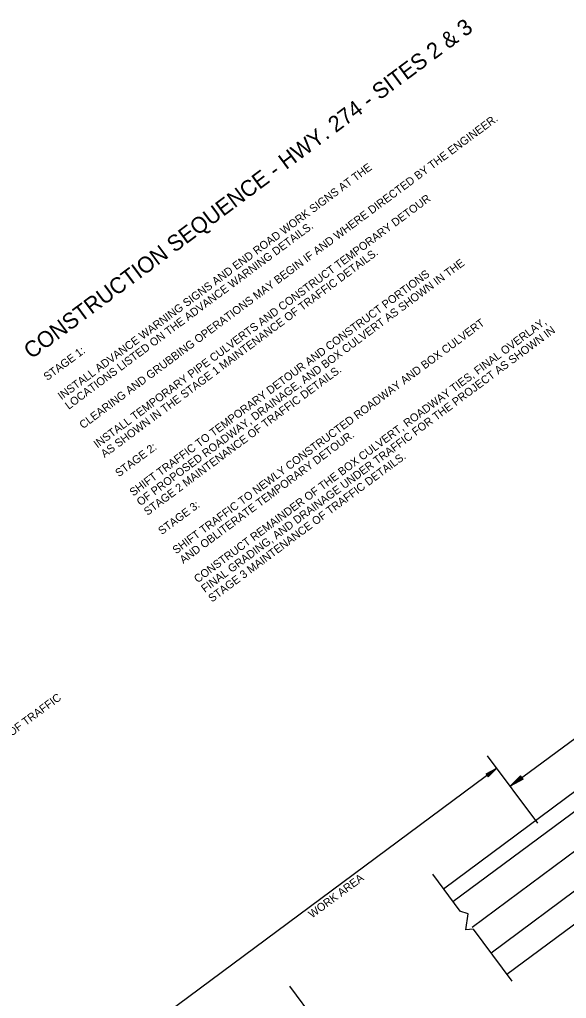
# Model space of a CAD drawing. Extents: x -238 to 1487, y -1123 to 446.
# Drawn here: x 374 to 784, y -485 to 249 of the extents above; entities that cross this region are included whole.
import ezdxf

# ---------------------------------------------------------------- set-up
doc = ezdxf.new("R2010")
doc.units = 0
doc.layers.add('R_Border Prem', color=7, linetype='Continuous')
doc.layers.add('R_Draft', color=7, linetype='Continuous')

msp = doc.modelspace()

# ---------------------------------------------------------------- linework, layer by layer
at = {"layer": 'R_Draft'}
for p, q in [((1242.19, 6.1), (691.32, -402.94)), ((1249.33, -3.51), (698.46, -412.55)), ((1263.6, -22.73), (712.73, -431.77)), ((1277.87, -41.95), (727, -450.98)), ((1289.76, -57.96), (738.89, -467)), ((741.43, -325.95), (902.01, -206.72)), ((762, -353.65), (724.45, -303.08)), ((731.32, -312.34), (483.94, -496.03)), ((723.23, -316.65), (731.32, -312.34)), ((723.37, -316.83), (730.11, -313.24)), ((723.5, -317.02), (728.85, -314.17)), ((723.64, -317.2), (727.64, -315.07)), ((724.44, -318.29), (727.64, -315.07)), ((724.58, -318.47), (728.85, -314.17)), ((724.72, -318.65), (730.11, -313.24)), ((724.85, -318.84), (731.32, -312.34)), ((723.23, -316.65), (724.85, -318.84)), ((723.78, -317.39), (726.41, -315.99)), ((723.92, -317.57), (725.19, -316.89)), ((724.17, -317.91), (725.19, -316.89)), ((724.31, -318.1), (726.41, -315.99)), ((749.07, -318.03), (741.43, -325.95)), ((751.06, -320.62), (741.43, -325.95)), ((749.23, -318.25), (742.87, -324.85)), ((750.89, -320.41), (742.87, -324.85)), ((749.41, -318.47), (744.36, -323.71)), ((750.72, -320.19), (744.36, -323.71)), ((749.57, -318.68), (745.79, -322.6)), ((750.55, -319.97), (745.79, -322.6)), ((749.74, -318.91), (747.26, -321.48)), ((750.38, -319.75), (747.26, -321.48)), ((749.91, -319.12), (748.7, -320.37)), ((750.22, -319.53), (748.7, -320.37)), ((751.06, -320.62), (749.07, -318.03)), ((683.14, -391.91), (703.68, -419.57)), ((713.68, -433.05), (742.65, -472.05)), ((605.08, -514.7), (576.11, -475.69))]:
    msp.add_line(p, q, dxfattribs=at)
msp.add_lwpolyline([(713.68, -433.05), (708.22, -433.6), (709.8, -421.6), (703.68, -419.57)], dxfattribs=at)

# ---------------------------------------------------------------- texts
at = {"layer": 'R_Border Prem'}
for s, height, rotation, p in [('CONSTRUCTION SEQUENCE - HWY. 274 - SITES 2 & 3', 12, 36.63408, (382.34, -6.04)), ('CLEARING AND GRUBBING OPERATIONS MAY BEGIN IF AND WHERE DIRECTED BY THE ENGINEER.', 6, 36.63408, (421.13, -58.2)), ('INSTALL ADVANCE WARNING SIGNS AND END ROAD WORK SIGNS AT THE ', 6, 36.63408, (405.02, -36.54)), ('INSTALL TEMPORARY PIPE CULVERTS AND CONSTRUCT TEMPORARY DETOUR', 6, 36.63408, (431.87, -72.65)), ('LOCATIONS LISTED ON THE ADVANCE WARNING DETAILS. ', 6, 36.63408, (410.39, -43.76)), ('AS SHOWN IN THE STAGE 1 MAINTENANCE OF TRAFFIC DETAILS.', 6, 36.63408, (437.24, -79.87)), ('OF PROPOSED ROADWAY, DRAINAGE, AND BOX CULVERT AS SHOWN IN THE', 6, 36.63408, (464.09, -115.98)), ('SHIFT TRAFFIC TO TEMPORARY DETOUR AND CONSTRUCT PORTIONS ', 6, 36.63408, (458.72, -108.76)), ('SHIFT TRAFFIC TO NEWLY CONSTRUCTED ROADWAY AND BOX CULVERT', 6, 36.63408, (490.94, -152.09)), ('CONSTRUCT REMAINDER OF THE BOX CULVERT, ROADWAY TIES, FINAL OVERLAY,', 6, 36.63408, (507.05, -173.76)), ('FINAL GRADING, AND DRAINAGE UNDER TRAFFIC FOR THE PROJECT AS SHOWN IN ', 6, 36.63408, (512.42, -180.98)), ('STAGE 1: ', 6, 36.63408, (394.28, -22.09)), ('STAGE 2 MAINTENANCE OF TRAFFIC DETAILS. ', 6, 36.63408, (469.46, -123.2)), ('AND OBLITERATE TEMPORARY DETOUR. ', 6, 36.63408, (496.31, -159.31)), ('STAGE 2:', 6, 36.63408, (447.98, -94.32)), ('STAGE 3 MAINTENANCE OF TRAFFIC DETAILS. ', 6, 36.63408, (517.79, -188.2)), ('STAGE 3:', 6, 36.63408, (480.2, -137.65)), ('DRAINAGE UNDER TRAFFIC FOR PROJECT AS SHOWN IN STAGE 3 MAINTENANCE OF TRAFFIC', 6, 36.63408, (108.44, -481.38)), ('WORK AREA', 6, 36.59533, (592.84, -425.1))]:
    msp.add_text(s, height=height, rotation=rotation, dxfattribs=at).set_placement(p)

doc.saveas('drawing.dxf')
